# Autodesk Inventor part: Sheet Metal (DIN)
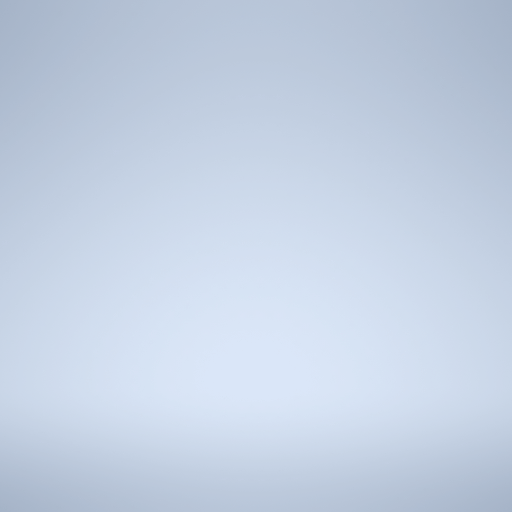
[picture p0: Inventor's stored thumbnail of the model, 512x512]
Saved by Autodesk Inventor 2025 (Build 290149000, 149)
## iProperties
Created: 2024-02
Part Number: Sheet Metal (DIN)
Material: Generico
Document SubType Name: Sheet Metal
Density: 1 g/cm^3
Sheet Metal Rule: Default_mm
Appearance: Default
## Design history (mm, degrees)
other parameters: "Spessore" = 0.5, "RaggioPiega" = 0.5 (= Spessore), "LarghezzaScaricoPiega" = 0.5 (= Spessore), "ProfonditàScaricoPiega" = 0.25 (= 0.5 x Spessore), "DimensioniScaricoAngolo" = 2 (= 4 x Spessore), "SeamGap" = 0.01, "ResiduoMinimo" = 1 (= 2 x Spessore), "RaggioTransizione" = 0.5 (= RaggioPiega), "Dimensione_raggio_Jacobi" = 0.5 (= RaggioPiega), "DimensioneGioco" = 0.5 (= Spessore)
